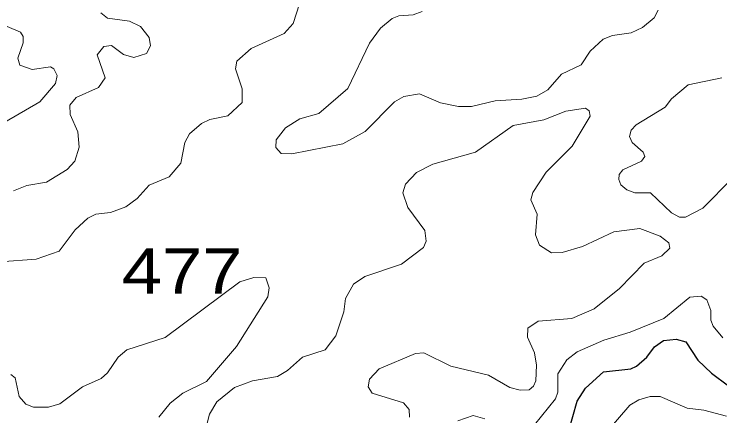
# Model space of a CAD drawing. Extents: x 577 to 602.9, y 7483.8 to 7511.6.
# Drawn here: x 587.677 to 588.93, y 7497.081 to 7497.794 of the extents above; entities that cross this region are included whole.
import ezdxf
from ezdxf.enums import TextEntityAlignment as Align

# ---------------------------------------------------------------- set-up
doc = ezdxf.new("R2010")
doc.units = 0
doc.header["$LTSCALE"] = 0.032
doc.layers.add('1', color=7, linetype='Continuous', lineweight=25)
doc.layers.add('2', color=7, linetype='Continuous', lineweight=13)
doc.layers.add('61', color=7, linetype='Continuous')

msp = doc.modelspace()

# ---------------------------------------------------------------- linework, layer by layer
at = {"layer": '1'}
msp.add_lwpolyline([(588.6615, 7497.0521), (588.6766, 7497.1069), (588.6917, 7497.13), (588.7235, 7497.1586), (588.772, 7497.1642), (588.7824, 7497.1689), (588.8007, 7497.1849), (588.8142, 7497.2031), (588.8301, 7497.2143), (588.8524, 7497.2167), (588.8698, 7497.2119), (588.8913, 7497.1793), (588.9152, 7497.1562), (588.9454, 7497.134)], dxfattribs=at)
at = {"layer": '2'}
for points in [[(587.6508, 7497.3542), (587.716, 7497.359), (587.7566, 7497.3733), (587.7852, 7497.4107), (587.8075, 7497.4314), (587.8218, 7497.4385), (587.848, 7497.4417), (587.8751, 7497.452), (587.895, 7497.4663), (587.9164, 7497.4902), (587.9522, 7497.5053), (587.9729, 7497.5292), (587.98, 7497.5657), (587.988, 7497.5816), (588.0095, 7497.5999), (588.0246, 7497.6071), (588.0564, 7497.6135), (588.0818, 7497.6373), (588.0818, 7497.6612), (588.0699, 7497.6969), (588.0723, 7497.7105), (588.0977, 7497.7327), (588.1566, 7497.7598), (588.1725, 7497.7773), (588.1836, 7497.8122)], [(587.8306, 7497.7963), (587.8425, 7497.7868), (587.8814, 7497.7812), (587.9013, 7497.7717), (587.9164, 7497.7526), (587.9188, 7497.7375), (587.9117, 7497.724), (587.8894, 7497.7168), (587.8711, 7497.7224), (587.8496, 7497.7383), (587.8361, 7497.7367), (587.8242, 7497.7216), (587.8385, 7497.681), (587.8266, 7497.6635), (587.7868, 7497.6461), (587.7757, 7497.6325), (587.7765, 7497.6158), (587.79, 7497.5848), (587.7924, 7497.5578), (587.7844, 7497.5331), (587.7709, 7497.518), (587.7343, 7497.4958), (587.6993, 7497.4894), (587.6755, 7497.4799)], [(588.8205, 7497.8011), (588.8134, 7497.7876), (588.7927, 7497.7701), (588.7728, 7497.7606), (588.7394, 7497.7558), (588.7227, 7497.7494), (588.6997, 7497.728), (588.6838, 7497.7041), (588.6488, 7497.6874), (588.6249, 7497.6596), (588.6051, 7497.6484), (588.5788, 7497.6429), (588.5311, 7497.6397), (588.489, 7497.6301), (588.4659, 7497.6301), (588.4341, 7497.6365), (588.3967, 7497.6524), (588.3689, 7497.6476), (588.3522, 7497.6381), (588.3005, 7497.5856), (588.2607, 7497.5634), (588.1701, 7497.5459), (588.151, 7497.5467), (588.1415, 7497.557), (588.1423, 7497.5705), (588.159, 7497.592), (588.1844, 7497.6079), (588.2178, 7497.6174), (588.2695, 7497.662), (588.3077, 7497.7423), (588.3275, 7497.7693), (588.3482, 7497.786), (588.3601, 7497.7908), (588.3856, 7497.7924), (588.4015, 7497.7987)], [(587.6644, 7497.7717), (587.6882, 7497.7621), (587.693, 7497.7542), (587.693, 7497.7431), (587.6834, 7497.716), (587.6866, 7497.7033), (587.7089, 7497.6954), (587.7415, 7497.7001), (587.7471, 7497.6969), (587.7534, 7497.685), (587.7502, 7497.6707), (587.7224, 7497.6381), (587.6604, 7497.6023)], [(588.9525, 7497.5029), (588.9001, 7497.4496), (588.8691, 7497.4337), (588.8587, 7497.4337), (588.8444, 7497.4409), (588.807, 7497.4767), (588.7792, 7497.4767), (588.7649, 7497.4822), (588.7545, 7497.491), (588.7506, 7497.5005), (588.7514, 7497.5093), (588.7577, 7497.5172), (588.7911, 7497.5331), (588.7967, 7497.5411), (588.7943, 7497.549), (588.7744, 7497.5657), (588.7697, 7497.5769), (588.7728, 7497.588), (588.7816, 7497.5975), (588.8333, 7497.6286), (588.8444, 7497.6437), (588.8738, 7497.6683), (588.9335, 7497.681)], [(588.1621, 7497.161), (588.1892, 7497.1849), (588.2289, 7497.1976), (588.248, 7497.223), (588.2623, 7497.2652), (588.2655, 7497.289), (588.2798, 7497.3145), (588.2997, 7497.328), (588.3649, 7497.3502), (588.4039, 7497.3797), (588.4086, 7497.3908), (588.4063, 7497.4099), (588.376, 7497.4504), (588.3673, 7497.4767), (588.3721, 7497.4918), (588.3912, 7497.5125), (588.4206, 7497.5276), (588.4961, 7497.549), (588.5629, 7497.596), (588.6178, 7497.6063), (588.6567, 7497.6214), (588.6917, 7497.627), (588.6981, 7497.6222), (588.6997, 7497.6127), (588.6679, 7497.5594), (588.6218, 7497.5133), (588.5979, 7497.4775), (588.5947, 7497.464), (588.6058, 7497.4385), (588.6027, 7497.4019), (588.6098, 7497.3836), (588.6313, 7497.3701), (588.6504, 7497.3709), (588.6862, 7497.3813), (588.7418, 7497.4075), (588.7879, 7497.4131), (588.8245, 7497.3995), (588.8396, 7497.3876), (588.8412, 7497.3781), (588.8269, 7497.3646), (588.7959, 7497.3518), (588.7522, 7497.3065), (588.7068, 7497.2707), (588.6671, 7497.2532), (588.6074, 7497.2485), (588.5892, 7497.2365), (588.5884, 7497.2206), (588.6011, 7497.1928), (588.6043, 7497.1705), (588.6035, 7497.1427), (588.5995, 7497.1332), (588.5915, 7497.1268), (588.5756, 7497.126), (588.5573, 7497.1308), (588.5192, 7497.153), (588.4524, 7497.1689), (588.4047, 7497.1928), (588.3896, 7497.1912), (588.3252, 7497.1642), (588.3077, 7497.1459), (588.3053, 7497.1324), (588.3124, 7497.1212), (588.3681, 7497.1037), (588.3784, 7497.0918), (588.3792, 7497.0783)], [(587.6707, 7497.1538), (587.6787, 7497.1483), (587.6858, 7497.1149), (587.6978, 7497.1014), (587.7113, 7497.0958), (587.7375, 7497.0958), (587.7582, 7497.1022), (587.798, 7497.1324), (587.8313, 7497.1467), (587.8425, 7497.157), (587.8616, 7497.1849), (587.8767, 7497.1976), (587.9451, 7497.2198), (588.0779, 7497.3184), (588.1025, 7497.3264), (588.124, 7497.3256), (588.1295, 7497.3081), (588.1272, 7497.2922), (588.0715, 7497.2039), (588.0182, 7497.1419), (587.9761, 7497.1212), (587.9538, 7497.1029), (587.9339, 7497.0783)], [(588.6011, 7497.0648), (588.6385, 7497.1109), (588.6424, 7497.1228), (588.6424, 7497.1554), (588.6583, 7497.1801), (588.6766, 7497.1944), (588.7243, 7497.2151), (588.7712, 7497.2294), (588.8309, 7497.2532), (588.877, 7497.2914), (588.8969, 7497.293), (588.9072, 7497.2866), (588.9144, 7497.2675), (588.9144, 7497.2508), (588.9184, 7497.2397), (588.9358, 7497.219)], [(588.0174, 7497.0584), (588.0238, 7497.0839), (588.0365, 7497.1053), (588.0683, 7497.1308), (588.1001, 7497.1427), (588.1446, 7497.1507), (588.1621, 7497.161)], [(588.9422, 7497.0799), (588.9017, 7497.091), (588.8722, 7497.0942), (588.8245, 7497.1149), (588.8062, 7497.1149), (588.7864, 7497.1093), (588.7705, 7497.0998), (588.7299, 7497.0529)], [(588.4651, 7497.0719), (588.4921, 7497.0815), (588.5128, 7497.0751)]]:
    msp.add_lwpolyline(points, dxfattribs=at)

# ---------------------------------------------------------------- texts
at = {"layer": '61', "width": 1.2}
msp.add_text('477', height=0.08, dxfattribs=at).set_placement((587.9751, 7497.2978), align=Align.CENTER)

doc.saveas('drawing.dxf')
